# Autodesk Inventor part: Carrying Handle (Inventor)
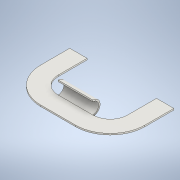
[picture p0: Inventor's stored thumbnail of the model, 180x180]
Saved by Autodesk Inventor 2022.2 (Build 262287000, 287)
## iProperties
Created: 2024-05
Part Number: Carrying Handle (Inventor)
Material: Generic
Document SubType Name: Modeling
Designer: JGG09
Density: 1 g/cm^3
Appearance: Default
Author: JGG09
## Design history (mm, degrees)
feature "Base1"
body "Solid1"
